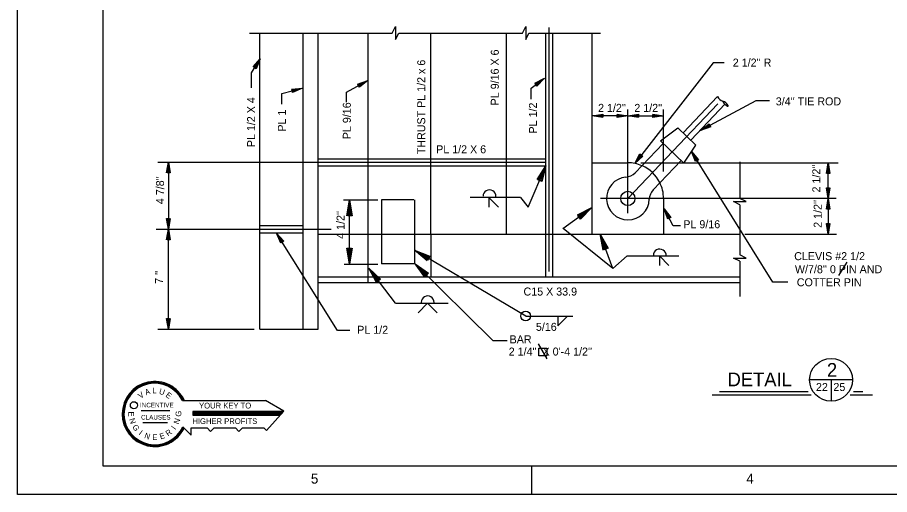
# Model space of a CAD drawing. Extents: x 0.1 to 13.5, y 0.1 to 9.5.
# Drawn here: x 0.13 to 5.22, y 0.13 to 2.91 of the extents above; entities that cross this region are included whole.
import ezdxf

# ---------------------------------------------------------------- set-up
doc = ezdxf.new("R2010")
doc.units = 0
for name, color, linetype in [('Level 1', 7, 'Continuous'), ('Level 13', 7, 'Continuous'), ('Level 25', 7, 'Continuous'), ('Level 3', 7, 'Continuous'), ('Level 44', 7, 'Continuous'), ('Level 50', 7, 'Continuous')]:
    doc.layers.add(name, color=color, linetype=linetype)

msp = doc.modelspace()

# ---------------------------------------------------------------- linework, layer by layer
at = {"layer": 'Level 1'}
for p, q in [((1.4787, 2.8196), (2.313, 2.8196)), ((2.3504, 2.8196), (3.0732, 2.8196)), ((3.1106, 2.8196), (3.5275, 2.8196)), ((3.6878, 2.336), (3.4795, 2.336)), ((3.6878, 2.336), (3.8961, 2.336)), ((3.7628, 2.0622), (4.9152, 2.0622)), ((2.0278, 1.8452), (2.2292, 1.8452)), ((4.9027, 1.8538), (3.5275, 1.8538)), ((4.371, 1.6455), (4.9048, 1.6455)), ((4.9198, 1.4035), (4.9686, 1.4823)), ((2.0317, 1.4702), (2.2292, 1.4702)), ((0.9435, 1.0913), (1.5063, 1.0913)), ((1.0876, 0.6742), (1.5733, 0.6742)), ((1.6793, 0.6116), (1.5733, 0.6742)), ((0.8476, 0.6159), (1.014, 0.6159)), ((1.6793, 0.6116), (1.5783, 0.4986)), ((1.678, 0.6099), (1.1493, 0.6099)), ((1.1493, 0.6099), (1.1493, 0.5892)), ((1.6726, 0.6042), (1.1493, 0.6042)), ((1.668, 0.5989), (1.1493, 0.5989)), ((1.663, 0.5932), (1.1493, 0.5932)), ((1.1493, 0.5892), (1.6593, 0.5892)), ((0.8563, 0.5456), (1.0003, 0.5456)), ((1.09, 0.5209), (1.1383, 0.4726)), ((1.1383, 0.4726), (1.1383, 0.5142)), ((1.1383, 0.5142), (1.232, 0.5142)), ((1.232, 0.5142), (1.2526, 0.4936)), ((1.2526, 0.4936), (1.2733, 0.5142)), ((1.2733, 0.5142), (1.3973, 0.5142)), ((1.3973, 0.5142), (1.418, 0.4936)), ((1.418, 0.4936), (1.4386, 0.5142)), ((1.4386, 0.5142), (1.5626, 0.5142)), ((1.5626, 0.5142), (1.5783, 0.4986)), ((3.125, 0.2917), (3.125, 0.125))]:
    msp.add_line(p, q, dxfattribs=at)
for points in [[(0.125, 9.4583), (13.4583, 9.4583), (13.4583, 0.125), (0.125, 0.125)], [(0.625, 9.2917), (13.2917, 9.2917), (13.2917, 0.2917), (0.625, 0.2917)]]:
    msp.add_lwpolyline(points, close=True, dxfattribs=at)
msp.add_circle((0.8045, 0.6467), 0.0205, dxfattribs=at)
for radius, start, end in [(0.19, 24.569, 334.4243), (0.1848, 25.3095, 334.4522), (0.1796, 26.0896, 335.5943)]:
    msp.add_arc((0.9263, 0.5952), radius, start, end, dxfattribs=at)
at = {"layer": 'Level 13'}
for points in [[(2.313, 2.8196), (2.3317, 2.8571), (2.3317, 2.7822), (2.3504, 2.8196)], [(3.0732, 2.8196), (3.0918, 2.8571), (3.0918, 2.7822), (3.1106, 2.8196)], [(4.3412, 1.817), (4.3037, 1.8356), (4.3786, 1.8356), (4.3412, 1.8544)], [(4.3412, 1.487), (4.3037, 1.5056), (4.3786, 1.5056), (4.3412, 1.5244)]]:
    msp.add_lwpolyline(points, dxfattribs=at)
for centre, radius, start, end in [((4.2573, 2.4712), 0.051, 206.1905, 252.9894), ((4.2904, 2.4397), 0.051, 199.7753, 246.5759), ((4.2275, 2.3737), 0.051, 26.1888, 72.9894), ((4.2711, 2.3951), 0.0025, 246.5759, 26.1888)]:
    msp.add_arc(centre, radius, start, end, dxfattribs=at)
at = {"layer": 'Level 25'}
for p, q in [((3.2295, 1.428), (3.2295, 2.852)), ((1.5389, 1.0913), (1.5389, 2.8196)), ((1.7928, 1.0913), (1.7928, 2.8196)), ((1.8807, 1.0913), (1.8807, 2.8196)), ((2.1723, 1.3622), (2.1723, 2.8196)), ((2.5374, 1.6455), (2.5374, 2.8196)), ((2.9795, 1.6455), (2.9795, 2.8196)), ((3.2086, 1.3955), (3.2086, 2.8196)), ((3.2503, 1.3955), (3.2503, 2.8196)), ((3.4795, 1.6455), (3.4795, 2.8196)), ((4.0101, 2.2374), (4.2115, 2.4487)), ((3.6878, 1.8538), (4.2136, 2.4056)), ((4.0554, 2.1943), (4.2567, 2.4056)), ((3.6878, 1.7674), (3.6878, 2.3736)), ((3.8961, 2.0107), (3.8961, 2.3736)), ((3.8786, 2.19), (3.9799, 2.2662)), ((3.9799, 2.2662), (4.0855, 2.1656)), ((3.8786, 2.19), (4.0143, 2.0607)), ((3.7301, 2.0039), (3.8937, 2.1756)), ((4.0143, 2.0607), (4.0855, 2.1656)), ((0.9435, 2.0653), (3.2086, 2.0653)), ((1.0061, 2.0653), (1.0061, 1.6747)), ((1.8807, 2.0861), (2.5374, 2.0861)), ((1.8807, 2.0445), (2.5374, 2.0445)), ((2.5374, 2.0861), (2.9795, 2.0861)), ((2.5374, 2.0445), (2.9795, 2.0445)), ((2.9795, 2.0861), (3.2086, 2.0861)), ((2.9795, 2.0445), (3.2086, 2.0445)), ((3.1062, 1.8021), (3.2086, 2.0445)), ((3.2086, 2.0445), (3.2086, 2.0445)), ((3.4795, 2.0622), (3.6878, 2.0622)), ((3.8357, 1.9033), (3.9993, 2.075)), ((4.3412, 2.0683), (4.3412, 1.8544)), ((4.8568, 1.8538), (4.8568, 2.0622)), ((3.1985, 2.0205), (3.1985, 2.0205)), ((2.064, 1.4702), (2.064, 1.8452)), ((2.4378, 1.8465), (2.2503, 1.8465)), ((2.2503, 1.8465), (2.2503, 1.4715)), ((2.4431, 1.8465), (2.4431, 1.4715)), ((3.0607, 1.8593), (2.7672, 1.8593)), ((2.8772, 1.8593), (2.8772, 1.8031)), ((2.8772, 1.8593), (2.9331, 1.8033)), ((3.0607, 1.8593), (3.1062, 1.8021)), ((3.8961, 1.8538), (3.8961, 1.6455)), ((4.8568, 1.8538), (4.8568, 1.6455)), ((3.3087, 1.6775), (3.4779, 1.8018)), ((3.457, 1.7864), (3.457, 1.7864)), ((3.4779, 1.8018), (3.4779, 1.8018)), ((4.3412, 1.817), (4.3412, 1.5244)), ((1.5389, 1.6955), (1.7928, 1.6955)), ((0.9352, 1.6747), (1.9554, 1.6747)), ((1.0061, 1.0913), (1.0061, 1.6747)), ((1.5389, 1.6538), (1.7928, 1.6538)), ((1.8807, 1.6455), (2.4431, 1.6455)), ((2.4431, 1.6455), (4.3412, 1.6455)), ((2.5374, 1.6455), (2.5374, 1.3955)), ((3.5996, 1.4447), (3.3097, 1.6782)), ((3.5996, 1.4447), (3.5255, 1.6457)), ((3.5255, 1.6457), (3.5255, 1.6457)), ((3.5345, 1.6213), (3.5345, 1.6213)), ((3.0916, 1.1673), (2.4434, 1.5516)), ((2.4434, 1.5516), (2.4434, 1.5516)), ((2.4658, 1.5383), (2.4658, 1.5383)), ((3.6842, 1.5188), (3.5996, 1.4447)), ((3.6842, 1.5188), (3.9856, 1.5188)), ((3.8717, 1.5188), (3.8717, 1.4625)), ((3.8717, 1.5188), (3.9276, 1.4628)), ((4.3412, 1.487), (4.3412, 1.281)), ((2.3312, 1.2422), (2.1755, 1.4471)), ((2.1755, 1.4471), (2.1755, 1.4471)), ((2.1913, 1.4264), (2.1913, 1.4264)), ((2.4378, 1.4715), (2.2503, 1.4715)), ((1.8807, 1.3955), (4.3412, 1.3955)), ((1.8807, 1.3622), (4.3412, 1.3622)), ((2.3312, 1.2422), (2.6385, 1.2422)), ((2.5188, 1.2421), (2.4634, 1.1867)), ((2.5187, 1.2422), (2.5746, 1.1863)), ((2.5189, 1.2422), (2.5188, 1.2421)), ((3.0916, 1.1673), (3.3674, 1.1673)), ((3.2791, 1.1673), (3.2791, 1.1111)), ((3.2791, 1.1111), (3.3349, 1.167)), ((1.5389, 1.0913), (1.8807, 1.0913)), ((3.2167, 0.9183), (3.167, 1.0044))]:
    msp.add_line(p, q, dxfattribs=at)
for points in [[(3.158, 1.9644), (3.2086, 2.0445), (3.1865, 1.9523), (3.1621, 1.9626), (3.1985, 2.0205), (3.1835, 1.9579), (3.1678, 1.9646), (3.1888, 1.9975), (3.1804, 1.9636), (3.174, 1.9663), (3.1787, 1.9735)], [(3.3934, 1.7589), (3.4779, 1.8018), (3.4117, 1.7339), (3.3961, 1.7553), (3.457, 1.7864), (3.412, 1.7403), (3.4019, 1.754), (3.4368, 1.7716), (3.4123, 1.7467), (3.4081, 1.7524), (3.4159, 1.7562)], [(3.5433, 1.5526), (3.5255, 1.6457), (3.5724, 1.5634), (3.5475, 1.5542), (3.5345, 1.6213), (3.5663, 1.5654), (3.5504, 1.5595), (3.5431, 1.5979), (3.5602, 1.5674), (3.5537, 1.565), (3.5521, 1.5735)], [(2.516, 1.4906), (2.4434, 1.5516), (2.5318, 1.5172), (2.5183, 1.4944), (2.4658, 1.5383), (2.5258, 1.515), (2.5171, 1.5003), (2.4873, 1.5256), (2.5198, 1.5127), (2.5162, 1.5067), (2.5097, 1.5123)], [(2.2198, 1.3633), (2.1755, 1.4471), (2.2444, 1.3821), (2.2233, 1.366), (2.1913, 1.4264), (2.238, 1.3822), (2.2245, 1.3719), (2.2064, 1.4065), (2.2316, 1.3824), (2.2261, 1.3781), (2.2221, 1.3858)]]:
    msp.add_lwpolyline(points, dxfattribs=at)
for centre, radius in [((3.6878, 1.8538), 0.0417), ((3.0916, 1.1673), 0.0281)]:
    msp.add_circle(centre, radius, dxfattribs=at)
for centre, radius, start, end in [((3.6878, 1.8538), 0.2083, 66.7678, 90), ((3.6878, 1.8538), 0.2083, 26.8277, 66.0536), ((3.6697, 2.0614), 0.0833, 274.9808, 316.3906), ((3.6878, 1.8538), 0.125, 94.9808, 357.8001), ((3.6878, 1.8538), 0.2083, 0, 26.4713), ((2.88, 1.8663), 0.0375, 358.4208, 180), ((3.896, 1.8458), 0.0833, 136.3891, 177.8001), ((3.8743, 1.5205), 0.0375, 358.4208, 180), ((2.5191, 1.2473), 0.0375, 358.4208, 180)]:
    msp.add_arc(centre, radius, start, end, dxfattribs=at)
at = {"layer": 'Level 3'}
for p, q in [((1.5333, 2.655), (1.5333, 2.655)), ((1.5424, 2.6698), (1.5424, 2.6698)), ((3.1871, 2.5456), (3.1871, 2.5456)), ((3.2009, 2.556), (3.2009, 2.556)), ((1.788, 2.4974), (1.788, 2.4974)), ((2.155, 2.5343), (2.155, 2.5343)), ((2.1701, 2.5427), (2.1701, 2.5427)), ((1.7712, 2.493), (1.7712, 2.493)), ((4.1119, 2.2514), (4.1119, 2.2514)), ((4.1272, 2.2596), (4.1272, 2.2596)), ((4.059, 2.1271), (4.059, 2.1271)), ((4.0682, 2.1124), (4.0682, 2.1124)), ((3.7285, 2.0583), (3.7285, 2.0583)), ((3.7391, 2.072), (3.7391, 2.072)), ((3.9003, 1.7938), (3.9003, 1.7938)), ((3.9084, 1.7785), (3.9084, 1.7785)), ((1.6376, 1.6515), (1.6376, 1.6515)), ((1.6468, 1.6368), (1.6468, 1.6368)), ((4.9988, 0.7949), (4.7488, 0.7949)), ((4.8738, 0.7949), (4.8738, 0.6699)), ((4.7403, 0.7253), (4.2233, 0.7253)), ((5.0585, 0.7253), (5.0055, 0.7253)), ((4.7587, 0.7045), (4.1803, 0.7045)), ((5.1148, 0.7045), (4.9862, 0.7045))]:
    msp.add_line(p, q, dxfattribs=at)
for points in [[(1.4921, 2.5005), (1.4921, 2.5878), (1.5424, 2.6698)], [(1.501, 2.622), (1.5424, 2.6698), (1.5186, 2.6112), (1.5036, 2.6205), (1.5333, 2.655), (1.5172, 2.6152), (1.5075, 2.6212), (1.5246, 2.6408), (1.5157, 2.6193), (1.5118, 2.6217), (1.5156, 2.626)], [(4.2494, 2.6455), (4.1859, 2.6455), (3.7285, 2.0583)], [(3.1243, 2.4344), (3.1243, 2.4979), (3.2009, 2.556)], [(3.145, 2.5266), (3.2009, 2.556), (3.1575, 2.5101), (3.1469, 2.5242), (3.1871, 2.5456), (3.1576, 2.5144), (3.1508, 2.5234), (3.1739, 2.5355), (3.1578, 2.5187), (3.1549, 2.5224), (3.1601, 2.525)], [(1.6678, 2.4048), (1.6678, 2.4658), (1.788, 2.4974)], [(1.725, 2.4916), (1.788, 2.4974), (1.7303, 2.4716), (1.7258, 2.4886), (1.7712, 2.493), (1.732, 2.4755), (1.7291, 2.4864), (1.7551, 2.4888), (1.7338, 2.4794), (1.7326, 2.4839), (1.7383, 2.4843)], [(2.046, 2.4166), (2.046, 2.4737), (2.1701, 2.5427)], [(2.1106, 2.5215), (2.1701, 2.5427), (2.1207, 2.5034), (2.1121, 2.5188), (2.155, 2.5343), (2.1214, 2.5076), (2.1159, 2.5175), (2.1404, 2.5262), (2.1221, 2.5118), (2.1198, 2.5159), (2.1253, 2.5178)], [(4.5138, 2.4233), (4.4344, 2.4233), (4.1119, 2.2514)], [(4.1717, 2.2716), (4.1119, 2.2514), (4.162, 2.2898), (4.1703, 2.2743), (4.1272, 2.2596), (4.1612, 2.2856), (4.1666, 2.2756), (4.1419, 2.2674), (4.1604, 2.2814), (4.1626, 2.2773), (4.1572, 2.2756)], [(3.7749, 2.1012), (3.7285, 2.0583), (3.7586, 2.1139), (3.7726, 2.103), (3.7391, 2.072), (3.7596, 2.1097), (3.7685, 2.1027), (3.7494, 2.0852), (3.7606, 2.1056), (3.7643, 2.1027), (3.76, 2.0988)], [(4.6222, 1.3654), (4.5349, 1.3654), (4.059, 2.1271)], [(4.0833, 2.0688), (4.059, 2.1271), (4.1008, 2.0797), (4.0858, 2.0703), (4.0682, 2.1124), (4.0965, 2.0802), (4.0869, 2.0742), (4.077, 2.0983), (4.0923, 2.0807), (4.0883, 2.0782), (4.0862, 2.0836)], [(3.9955, 1.6933), (3.9532, 1.6933), (3.9003, 1.7938)], [(3.9202, 1.7339), (3.9003, 1.7938), (3.9385, 1.7435), (3.9229, 1.7353), (3.9084, 1.7785), (3.9343, 1.7443), (3.9243, 1.739), (3.9162, 1.7638), (3.9301, 1.7451), (3.926, 1.7429), (3.9242, 1.7484)], [(2.0647, 1.0838), (1.9929, 1.0838), (1.6376, 1.6515)], [(1.6619, 1.5931), (1.6376, 1.6515), (1.6794, 1.6041), (1.6644, 1.5947), (1.6468, 1.6368), (1.6752, 1.6046), (1.6656, 1.5986), (1.6556, 1.6226), (1.6709, 1.6051), (1.667, 1.6026), (1.6648, 1.6079)]]:
    msp.add_lwpolyline(points, dxfattribs=at)
msp.add_circle((4.8738, 0.7949), 0.125, dxfattribs=at)
at = {"layer": 'Level 44'}
for q in [(2.4468, 1.4715), (2.9837, 1.0251)]:
    msp.add_line((2.9004, 1.0251), q, dxfattribs=at)
msp.add_lwpolyline([(3.1676, 0.9801), (3.2153, 0.9801), (3.2153, 0.9345), (3.1676, 0.9345)], close=True, dxfattribs=at)
at = {"layer": 'Level 50'}
for p, q in [((3.4795, 2.336), (3.4795, 2.336)), ((3.4968, 2.336), (3.4968, 2.336)), ((3.6705, 2.336), (3.6705, 2.336)), ((3.6878, 2.336), (3.6878, 2.336)), ((3.6878, 2.336), (3.6878, 2.336)), ((3.7051, 2.336), (3.7051, 2.336)), ((3.8788, 2.336), (3.8788, 2.336)), ((3.8961, 2.336), (3.8961, 2.336)), ((1.0061, 2.0653), (1.0061, 2.0653)), ((1.0061, 2.048), (1.0061, 2.048)), ((4.8568, 2.0622), (4.8568, 2.0622)), ((4.8568, 2.0448), (4.8568, 2.0448)), ((2.064, 1.8452), (2.064, 1.8452)), ((4.8568, 1.8712), (4.8568, 1.8712)), ((4.8568, 1.8538), (4.8568, 1.8538)), ((4.8568, 1.8538), (4.8568, 1.8538)), ((4.8568, 1.8365), (4.8568, 1.8365)), ((2.064, 1.8192), (2.064, 1.8192)), ((1.0061, 1.692), (1.0061, 1.692)), ((1.0061, 1.6747), (1.0061, 1.6747)), ((1.0061, 1.6747), (1.0061, 1.6747)), ((1.0061, 1.6573), (1.0061, 1.6573)), ((4.8568, 1.6628), (4.8568, 1.6628)), ((4.8568, 1.6455), (4.8568, 1.6455)), ((2.064, 1.4962), (2.064, 1.4962)), ((2.064, 1.4702), (2.064, 1.4702)), ((2.4468, 1.4715), (2.4468, 1.4715)), ((2.4654, 1.4533), (2.4654, 1.4533)), ((1.0061, 1.1087), (1.0061, 1.1087)), ((1.0061, 1.0913), (1.0061, 1.0913))]:
    msp.add_line(p, q, dxfattribs=at)
for points in [[(3.5418, 2.3257), (3.4795, 2.336), (3.5418, 2.3464), (3.5418, 2.3287), (3.4968, 2.336), (3.5391, 2.343), (3.5391, 2.3317), (3.5135, 2.336), (3.5365, 2.3397), (3.5365, 2.335), (3.5308, 2.336)], [(3.6255, 2.3464), (3.6878, 2.336), (3.6255, 2.3257), (3.6255, 2.3434), (3.6705, 2.336), (3.6281, 2.329), (3.6281, 2.3404), (3.6538, 2.336), (3.6308, 2.3324), (3.6308, 2.337), (3.6365, 2.336)], [(3.7501, 2.3257), (3.6878, 2.336), (3.7501, 2.3464), (3.7501, 2.3287), (3.7051, 2.336), (3.7475, 2.343), (3.7475, 2.3317), (3.7218, 2.336), (3.7448, 2.3397), (3.7448, 2.335), (3.7391, 2.336)], [(3.8338, 2.3464), (3.8961, 2.336), (3.8338, 2.3257), (3.8338, 2.3434), (3.8788, 2.336), (3.8365, 2.329), (3.8365, 2.3404), (3.8621, 2.336), (3.8391, 2.3324), (3.8391, 2.337), (3.8448, 2.336)], [(0.9958, 2.003), (1.0061, 2.0653), (1.0164, 2.003), (0.9988, 2.003), (1.0061, 2.048), (1.0131, 2.0056), (1.0018, 2.0056), (1.0061, 2.0313), (1.0098, 2.0083), (1.0051, 2.0083), (1.0061, 2.014)], [(4.8464, 1.9998), (4.8568, 2.0622), (4.8671, 1.9998), (4.8494, 1.9998), (4.8568, 2.0448), (4.8638, 2.0025), (4.8524, 2.0025), (4.8568, 2.0282), (4.8604, 2.0052), (4.8558, 2.0052), (4.8568, 2.0108)], [(4.8671, 1.9162), (4.8568, 1.8538), (4.8464, 1.9162), (4.8641, 1.9162), (4.8568, 1.8712), (4.8498, 1.9135), (4.8611, 1.9135), (4.8568, 1.8878), (4.8531, 1.9108), (4.8578, 1.9108), (4.8568, 1.9052)], [(2.0485, 1.7517), (2.064, 1.8452), (2.0795, 1.7517), (2.053, 1.7517), (2.064, 1.8192), (2.0745, 1.7557), (2.0575, 1.7557), (2.064, 1.7942), (2.0695, 1.7597), (2.0625, 1.7597), (2.064, 1.7682)], [(4.8464, 1.7915), (4.8568, 1.8538), (4.8671, 1.7915), (4.8494, 1.7915), (4.8568, 1.8365), (4.8638, 1.7942), (4.8524, 1.7942), (4.8568, 1.8198), (4.8604, 1.7968), (4.8558, 1.7968), (4.8568, 1.8025)], [(1.0164, 1.737), (1.0061, 1.6747), (0.9958, 1.737), (1.0134, 1.737), (1.0061, 1.692), (0.9991, 1.7343), (1.0104, 1.7343), (1.0061, 1.7087), (1.0024, 1.7317), (1.0071, 1.7317), (1.0061, 1.726)], [(4.8671, 1.7078), (4.8568, 1.6455), (4.8464, 1.7078), (4.8641, 1.7078), (4.8568, 1.6628), (4.8498, 1.7052), (4.8611, 1.7052), (4.8568, 1.6795), (4.8531, 1.7025), (4.8578, 1.7025), (4.8568, 1.6968)], [(0.9958, 1.6123), (1.0061, 1.6747), (1.0164, 1.6123), (0.9988, 1.6123), (1.0061, 1.6573), (1.0131, 1.615), (1.0018, 1.615), (1.0061, 1.6407), (1.0098, 1.6177), (1.0051, 1.6177), (1.0061, 1.6233)], [(2.0795, 1.5637), (2.064, 1.4702), (2.0485, 1.5637), (2.075, 1.5637), (2.064, 1.4962), (2.0535, 1.5597), (2.0705, 1.5597), (2.064, 1.5212), (2.0585, 1.5557), (2.0655, 1.5557), (2.064, 1.5472)], [(2.5026, 1.3949), (2.4468, 1.4715), (2.5243, 1.417), (2.5058, 1.3981), (2.4654, 1.4533), (2.518, 1.4162), (2.5061, 1.4041), (2.4832, 1.4358), (2.5116, 1.4155), (2.5067, 1.4105), (2.5017, 1.4175)], [(1.0164, 1.1537), (1.0061, 1.0913), (0.9958, 1.1537), (1.0134, 1.1537), (1.0061, 1.1087), (0.9991, 1.151), (1.0104, 1.151), (1.0061, 1.1253), (1.0024, 1.1483), (1.0071, 1.1483), (1.0061, 1.1427)]]:
    msp.add_lwpolyline(points, dxfattribs=at)

# ---------------------------------------------------------------- texts
at = {"layer": 'Level 1'}
for s, height, p in [("2 1/2'' R", 0.0467, (4.3002, 2.6238)), ("3/4'' TIE ROD", 0.046698, (4.5512, 2.3973)), ("2 1/2''", 0.0467, (3.514, 2.3593)), ("2 1/2''", 0.0467, (3.7256, 2.3593)), ('PL 9/16', 0.0467, (4.0114, 1.68)), ('CLEVIS #2 1/2', 0.046698, (4.6588, 1.4936)), ("W/7/8'' 0 PIN AND", 0.046698, (4.6629, 1.4172)), ('COTTER PIN', 0.0467, (4.674, 1.3411)), ('L', 0.0333, (0.9126, 0.7156)), ('INCENTIVE', 0.02667, (0.8403, 0.6342)), ('YOUR KEY TO', 0.033333, (1.185, 0.6276)), ('CLAUSES', 0.02667, (0.8466, 0.5629)), ('HIGHER PROFITS', 0.033333, (1.146, 0.5369)), ('E', 0.0333, (0.912, 0.4429)), ('5', 0.0584, (1.8378, 0.189)), ('4', 0.0584, (4.3795, 0.189))]:
    msp.add_text(s, height=height, dxfattribs=at).set_placement(p)
for s, height, rotation, p in [("2 1/2''", 0.0467, 90, (4.8114, 1.8888)), ("2 1/2''", 0.0467, 90, (4.8193, 1.6826)), ('V', 0.0333, 35.9204, (0.8433, 0.6832)), ('A', 0.0333, 18.0731, (0.8743, 0.7046)), ('U', 0.0333, 342.1107, (0.9486, 0.7142)), ('E', 0.0333, 323.9298, (0.9866, 0.6992)), ('G', 0.0333, 90, (1.0813, 0.5799)), ('E', 0.0333, 270, (0.7726, 0.6099)), ('N', 0.0333, 288.0821, (0.7763, 0.5646)), ('N', 0.0333, 71.9179, (1.0666, 0.5329)), ('G', 0.0333, 306.0537, (0.7933, 0.5192)), ('I', 0.0333, 53.5836, (1.046, 0.5002)), ('I', 0.0333, 323.5836, (0.8303, 0.4769)), ('N', 0.0333, 341.9179, (0.863, 0.4559)), ('E', 0.0333, 18.2241, (0.961, 0.4466)), ('R', 0.0333, 36.2206, (1.0046, 0.4636))]:
    msp.add_text(s, height=height, rotation=rotation, dxfattribs=at).set_placement(p)
at = {"layer": 'Level 25'}
for s, height, p in [('PL 9/16 X 6', 0.046698, (2.9343, 2.3972)), ('THRUST PL 1/2 x 6', 0.046698, (2.5053, 2.1121)), ('PL 1/2 X 4', 0.0467, (1.5122, 2.1534)), ('PL 9/16', 0.0467, (2.0708, 2.1999)), ('PL 1/2', 0.0467, (3.1575, 2.233)), ('PL 1', 0.0467, (1.6918, 2.2442)), ("4 7/8''", 0.0467, (0.9808, 1.8206)), ("4 1/2''", 0.0467, (2.0344, 1.6182)), ("7 ''", 0.0467, (0.9749, 1.3553))]:
    msp.add_text(s, height=height, rotation=90, dxfattribs=at).set_placement(p)
for s, height, p in [('PL 1/2 X 6', 0.0467, (2.5689, 2.1175)), ('C15 X 33.9', 0.0467, (3.0788, 1.287)), ('5/16', 0.0467, (3.1511, 1.0809)), ('PL 1/2', 0.0467, (2.1081, 1.0637)), ('BAR ', 0.0467, (2.9977, 1.0081)), ("2 1/4''  X 0'-4 1/2''", 0.046698, (2.9925, 0.9365))]:
    msp.add_text(s, height=height, dxfattribs=at).set_placement(p)
at = {"layer": 'Level 3'}
for s, height, p in [('2', 0.08, (4.8497, 0.8127)), ('DETAIL', 0.08, (4.2701, 0.7573)), ('22', 0.04679, (4.7856, 0.7296)), ('25', 0.04679, (4.8875, 0.7296))]:
    msp.add_text(s, height=height, dxfattribs=at).set_placement(p)

doc.saveas('drawing.dxf')
